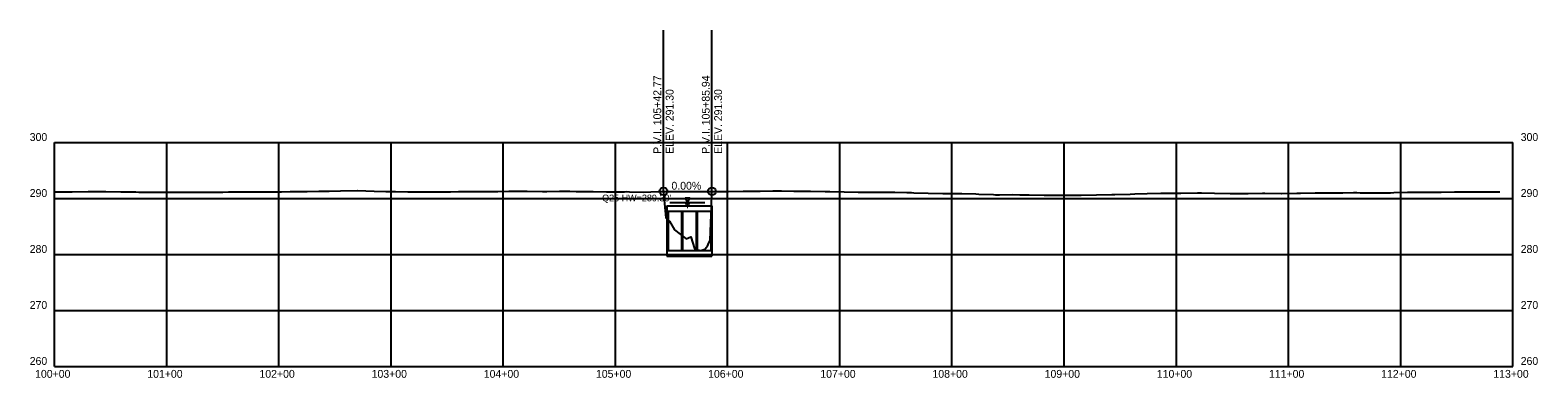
# Model space of a CAD drawing. Extents: x 1768942 to 1774819, y 723037 to 732099.
# Drawn here: x 1771894 to 1773238, y 724919 to 725230 of the extents above; entities that cross this region are included whole.
import ezdxf

# ---------------------------------------------------------------- set-up
doc = ezdxf.new("R2010")
doc.units = 0
for name, color, linetype in [('R_Axis', 7, 'Continuous'), ('R_Axis Annot', 7, 'Continuous'), ('R_Exist Surface', 7, 'Continuous'), ('R_Grid', 7, 'Continuous'), ('R_Proposed Road', 7, 'Continuous'), ('R_Vert Alg', 7, 'Continuous'), ('R_Vert Alg Annot', 7, 'Continuous'), ('R_Water', 7, 'Continuous'), ('R_Water Annot', 7, 'Continuous')]:
    doc.layers.add(name, color=color, linetype=linetype)

msp = doc.modelspace()

# ---------------------------------------------------------------- linework, layer by layer
at = {"layer": 'R_Axis'}
for p, q in [((1771915.5, 724929.2), (1771915.5, 725129.2)), ((1773215.5, 724929.2), (1773215.5, 725129.2)), ((1771915.5, 724929.2), (1773215.5, 724929.2))]:
    msp.add_line(p, q, dxfattribs=at)
at = {"layer": 'R_Exist Surface'}
msp.add_lwpolyline([(1771915.5, 725085.4), (1771930.2, 725085.3), (1771930.5, 725085.3), (1771931.2, 725085.3), (1771945.5, 725085.5), (1771947.1, 725085.5), (1771960.5, 725085.5), (1771961.3, 725085.5), (1771974.6, 725085.2), (1771974.6, 725085.2), (1771975.4, 725085.2), (1771975.5, 725085.2), (1771987.9, 725085.2), (1771990.5, 725085.1), (1772000.3, 725085.1), (1772005.5, 725085.1), (1772018.1, 725085), (1772020.1, 725084.9), (1772020.5, 725084.9), (1772023.1, 725084.9), (1772035.5, 725084.9), (1772044.3, 725085), (1772050.5, 725084.9), (1772059.5, 725085), (1772065.5, 725085.1), (1772070.6, 725085.2), (1772080.5, 725085.2), (1772089.9, 725085.3), (1772095.5, 725085.3), (1772101.6, 725085.3), (1772110.5, 725085.2), (1772117.9, 725085.4), (1772125.5, 725085.7), (1772133.5, 725085.7), (1772140.5, 725085.7), (1772151.1, 725085.9), (1772155.5, 725085.9), (1772160.2, 725086), (1772170.5, 725086.2), (1772185.5, 725086.3), (1772185.5, 725086.3), (1772185.6, 725086.3), (1772200.5, 725086), (1772210.9, 725085.7), (1772215.5, 725085.6), (1772219.5, 725085.6), (1772230.5, 725085.4), (1772243.7, 725085.4), (1772245.5, 725085.4), (1772246.5, 725085.4), (1772260.5, 725085.3), (1772268.5, 725085.4), (1772275.5, 725085.6), (1772288.3, 725085.7), (1772290.3, 725085.7), (1772290.5, 725085.7), (1772290.7, 725085.7), (1772292.3, 725085.7), (1772295.3, 725085.7), (1772295.3, 725085.7), (1772304.1, 725085.7), (1772305.5, 725085.7), (1772310.6, 725085.7), (1772320.5, 725085.8), (1772328.4, 725085.8), (1772334.9, 725085.8), (1772335.5, 725085.8), (1772336.8, 725085.8), (1772350.5, 725085.6), (1772354.3, 725085.6), (1772365.5, 725086), (1772374.7, 725085.8), (1772380.5, 725085.7), (1772384.9, 725085.6), (1772395.5, 725085.5), (1772407.4, 725085.3), (1772410.5, 725085.3), (1772423.5, 725085.4), (1772425.5, 725085.5), (1772428, 725085.4), (1772440.5, 725085.1), (1772453.5, 725085.7), (1772455.5, 725085.7), (1772456.8, 725085.7), (1772458.1, 725085.6), (1772458.3, 725085.7), (1772458.4, 725084.5), (1772460.3, 725062), (1772463.6, 725059.2), (1772468.2, 725051.4), (1772476.9, 725044.4), (1772478.6, 725043.4), (1772482.7, 725045.1), (1772482.7, 725045.1), (1772486, 725034.6), (1772486.1, 725034.2), (1772491.2, 725033), (1772491.4, 725032.9), (1772491.5, 725032.9), (1772495.1, 725034.1), (1772497, 725036.1), (1772497.6, 725036.7), (1772498, 725038.2), (1772499.8, 725042.1), (1772501, 725072.5), (1772501.4, 725083.8), (1772501.5, 725085.7), (1772502.2, 725085.7), (1772502.4, 725085.6), (1772514.4, 725085.7), (1772516.4, 725085.7), (1772529.4, 725085.8), (1772532, 725085.8), (1772544.4, 725085.9), (1772555.8, 725086.1), (1772559.4, 725086.2), (1772563.5, 725086.1), (1772574.4, 725086), (1772576.6, 725086), (1772589.4, 725086), (1772602.4, 725085.7), (1772604.4, 725085.7), (1772606.5, 725085.6), (1772619.4, 725085.2), (1772631.8, 725085), (1772634.4, 725085), (1772640.4, 725085), (1772649.4, 725085), (1772657.4, 725085), (1772664.4, 725084.9), (1772675.1, 725084.7), (1772677.7, 725084.6), (1772679.4, 725084.6), (1772681.5, 725084.5), (1772694.4, 725084.2), (1772707.2, 725083.9), (1772709.4, 725083.9), (1772712.7, 725083.9), (1772724.4, 725083.9), (1772736.9, 725083.4), (1772739.4, 725083.3), (1772752.5, 725082.8), (1772754.4, 725082.7), (1772755.1, 725082.7), (1772758, 725082.7), (1772769.4, 725082.8), (1772775.9, 725082.7), (1772784.4, 725082.6), (1772797.8, 725082.3), (1772799.4, 725082.3), (1772799.5, 725082.3), (1772799.8, 725082.3), (1772814.4, 725082.2), (1772827.5, 725082.4), (1772829.4, 725082.4), (1772830.8, 725082.4), (1772844.4, 725082.5), (1772858.1, 725082.9), (1772859.4, 725082.9), (1772860.6, 725083), (1772874.4, 725083.3), (1772878.4, 725083.5), (1772889.4, 725083.8), (1772901.6, 725084), (1772904.4, 725084), (1772919.2, 725084.1), (1772919.4, 725084.1), (1772919.6, 725084.1), (1772934.4, 725084.3), (1772934.5, 725084.3), (1772937.8, 725084.3), (1772949.4, 725084.1), (1772963.5, 725083.9), (1772964.4, 725083.9), (1772965.5, 725083.9), (1772979.4, 725083.9), (1772992.2, 725084.1), (1772994.4, 725084.1), (1773009, 725083.8), (1773009.4, 725083.8), (1773023, 725084.1), (1773024.4, 725084.1), (1773026.2, 725084.1), (1773039.4, 725084.4), (1773043.4, 725084.4), (1773054.4, 725084.3), (1773060.2, 725084.5), (1773062.4, 725084.5), (1773062.9, 725084.5), (1773064, 725084.5), (1773073.3, 725084.6), (1773076.5, 725084.6), (1773079.4, 725084.5), (1773091.5, 725084.5), (1773099.8, 725084.5), (1773106.5, 725084.5), (1773109.5, 725084.6), (1773121.5, 725084.9), (1773132.8, 725084.9), (1773136.5, 725084.9), (1773148, 725084.9), (1773151.5, 725084.9), (1773163.5, 725085.3), (1773166.1, 725085.3), (1773166.5, 725085.3), (1773179.6, 725085.2), (1773181.5, 725085.2), (1773182.9, 725085.2), (1773188.6, 725085.3), (1773196.5, 725085.2), (1773204, 725085.2)], dxfattribs=at)
at = {"layer": 'R_Grid'}
for p, q in [((1771915.5, 725129.2), (1773215.5, 725129.2)), ((1771915.5, 725129.2), (1773215.5, 725129.2)), ((1772015.5, 724929.2), (1772015.5, 725129.2)), ((1772115.5, 724929.2), (1772115.5, 725129.2)), ((1772215.5, 724929.2), (1772215.5, 725129.2)), ((1772315.5, 724929.2), (1772315.5, 725129.2)), ((1772415.5, 724929.2), (1772415.5, 725129.2)), ((1772515.5, 724929.2), (1772515.5, 725129.2)), ((1772615.5, 724929.2), (1772615.5, 725129.2)), ((1772715.5, 724929.2), (1772715.5, 725129.2)), ((1772815.5, 724929.2), (1772815.5, 725129.2)), ((1772915.5, 724929.2), (1772915.5, 725129.2)), ((1773015.5, 724929.2), (1773015.5, 725129.2)), ((1773115.5, 724929.2), (1773115.5, 725129.2)), ((1771915.5, 725079.2), (1773215.5, 725079.2)), ((1771915.5, 725029.2), (1773215.5, 725029.2)), ((1771915.5, 724979.2), (1773215.5, 724979.2))]:
    msp.add_line(p, q, dxfattribs=at)
at = {"layer": 'R_Proposed Road'}
msp.add_lwpolyline([(1772477.7, 725079.7), (1772479.7, 725075.7), (1772481.7, 725079.7), (1772477.7, 725079.7)], dxfattribs=at)
at = {"layer": 'R_Vert Alg'}
for p, q in [((1772458.3, 725110.7), (1772458.3, 725229.7)), ((1772501.5, 725110.7), (1772501.5, 725229.7)), ((1772458.3, 725085.7), (1772458.3, 725110.7)), ((1772501.5, 725085.7), (1772501.5, 725110.7)), ((1772458.3, 725085.7), (1772501.5, 725085.7))]:
    msp.add_line(p, q, dxfattribs=at)
for centre in [(1772458.3, 725085.7), (1772501.5, 725085.7)]:
    msp.add_circle(centre, 3.5, dxfattribs=at)
at = {"layer": 'R_Water'}
for p, q in [((1772458.3, 725085.7), (1772501.5, 725085.7)), ((1772461.4, 725072.9), (1772501.4, 725072.9)), ((1772461.4, 725072.9), (1772461.4, 725027.9)), ((1772464, 725075.7), (1772495.3, 725075.7)), ((1772477.7, 725074.7), (1772481.7, 725074.7)), ((1772478.7, 725073.7), (1772480.7, 725073.7)), ((1772479.2, 725072.7), (1772480.2, 725072.7)), ((1772479.4, 725071.7), (1772479.9, 725071.7)), ((1772501.4, 725072.9), (1772501.4, 725027.9)), ((1772462.4, 725067.9), (1772501.4, 725067.9)), ((1772462.4, 725067.9), (1772462.4, 725032.9)), ((1772474.4, 725067.9), (1772474.4, 725032.9)), ((1772475.4, 725067.9), (1772475.4, 725032.9)), ((1772487.4, 725067.9), (1772487.4, 725032.9)), ((1772488.4, 725067.9), (1772488.4, 725033.3)), ((1772500.4, 725067.9), (1772500.4, 725032.9)), ((1772461.4, 725032.9), (1772501.4, 725032.9)), ((1772461.4, 725027.9), (1772501.4, 725027.9))]:
    msp.add_line(p, q, dxfattribs=at)

# ---------------------------------------------------------------- texts
at = {"layer": 'R_Axis Annot'}
for s, p in [('300', (1771893.3, 725130.7)), ('300', (1771893.3, 725130.7)), ('300', (1773222.5, 725130.7)), ('300', (1773222.5, 725130.7)), ('290', (1771893.3, 725080.7)), ('290', (1773222.5, 725080.7)), ('280', (1771893.3, 725030.7)), ('280', (1773222.5, 725030.7)), ('270', (1771893.3, 724980.7)), ('270', (1773222.5, 724980.7)), ('260', (1771893.3, 724930.7)), ('260', (1773222.5, 724930.7)), ('100+00', (1771898.1, 724919.2)), ('101+00', (1771998.1, 724919.2)), ('102+00', (1772098.1, 724919.2)), ('103+00', (1772198.1, 724919.2)), ('104+00', (1772298.1, 724919.2)), ('105+00', (1772398.1, 724919.2)), ('106+00', (1772498.1, 724919.2)), ('107+00', (1772598.1, 724919.2)), ('108+00', (1772698.1, 724919.2)), ('109+00', (1772798.1, 724919.2)), ('110+00', (1772898.1, 724919.2)), ('111+00', (1772998.1, 724919.2)), ('112+00', (1773098.1, 724919.2)), ('113+00', (1773198.1, 724919.2))]:
    msp.add_text(s, height=7, dxfattribs=at).set_placement(p)
at = {"layer": 'R_Vert Alg Annot'}
for s, rotation, p in [('P.V.I. 105+42.77', 90, (1772456.3, 725119.2)), ('P.V.I. 105+85.94', 90, (1772499.5, 725119.2)), ('ELEV. 291.30', 90, (1772467.3, 725119.2)), ('ELEV. 291.30', 90, (1772510.5, 725119.2)), ('0.00%', 360, (1772465.4, 725087.2))]:
    msp.add_text(s, height=7, rotation=rotation, dxfattribs=at).set_placement(p)
at = {"layer": 'R_Water Annot'}
msp.add_text("Q25 HW=289.30'", height=6, dxfattribs=at).set_placement((1772403.6, 725076.8))

doc.saveas('drawing.dxf')
